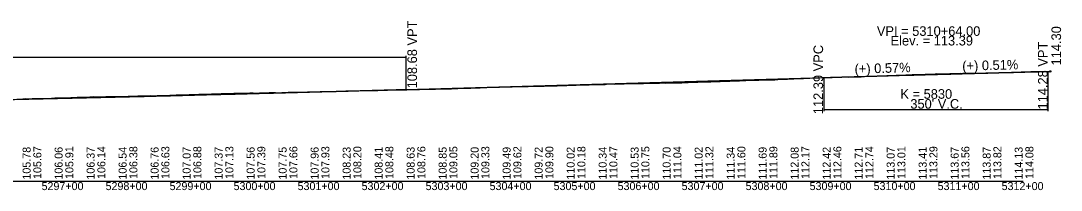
# Model space of a CAD drawing. Extents: x 2121671 to 2169879, y 557274 to 599957.
# Drawn here: x 2159202 to 2160827, y 598693 to 598958 of the extents above; entities that cross this region are included whole.
import ezdxf

# ---------------------------------------------------------------- set-up
doc = ezdxf.new("R2010")
doc.units = 0
for name, color, linetype in [('RD_DDB_GradeTX', 7, 'Continuous'), ('RD_DDB_Profile_EX', 7, 'Continuous'), ('RD_DDB_Profile_Lbl', 7, 'Continuous'), ('RD_DDB_Profile_PR', 7, 'Continuous'), ('RD_DDB_StaTX', 7, 'Continuous'), ('RD_DDB_StripGrade', 7, 'Continuous'), ('RD_DDB_VCLbl', 7, 'Continuous'), ('RD_GPK_Profile_Cell', 7, 'Continuous')]:
    doc.layers.add(name, color=color, linetype=linetype)

msp = doc.modelspace()

# ---------------------------------------------------------------- linework, layer by layer
at = {"layer": 'RD_DDB_GradeTX'}
for p, q in [((2160570.3, 598872.7), (2160631.2, 598874.4)), ((2160694.2, 598876), (2160633.2, 598874.4))]:
    msp.add_line(p, q, dxfattribs=at)
for centre in [(2160632.2, 598874.4), (2160810.4, 598878.9)]:
    msp.add_circle(centre, 1, dxfattribs=at)
at = {"layer": 'RD_DDB_Profile_EX'}
for points in [[(2160504.8, 598870.7), (2160509.8, 598870.7), (2160514.8, 598870.7), (2160519.8, 598871.2), (2160524.8, 598871.4), (2160529.8, 598871.6), (2160534.8, 598871.7), (2160539.8, 598871.9), (2160544.8, 598872), (2160549.8, 598872.2), (2160554.8, 598872.4), (2160559.8, 598872.6), (2160564.8, 598872.7), (2160569.8, 598872.8), (2160574.8, 598873.1), (2160579.8, 598873.3), (2160584.8, 598873.5), (2160589.8, 598873.8), (2160594.8, 598874), (2160599.8, 598874.2), (2160604.8, 598874.3), (2160609.8, 598874.3), (2160614.8, 598874.5), (2160619.8, 598874.5), (2160624.8, 598874.7), (2160629.8, 598874.8), (2160634.8, 598874.9), (2160639.8, 598874.9), (2160644.8, 598875.1), (2160649.8, 598875.3), (2160654.8, 598875.3), (2160659.8, 598875.3), (2160664.8, 598875.5), (2160669.8, 598876), (2160674.8, 598875.8), (2160679.8, 598875.7), (2160684.8, 598876), (2160689.8, 598876.1), (2160694.8, 598876.2), (2160699.8, 598876.3), (2160704.8, 598876.4), (2160709.8, 598876.5), (2160714.8, 598876.7), (2160719.8, 598876.9), (2160724.8, 598876.9), (2160729.8, 598877.1), (2160734.8, 598877.2), (2160739.8, 598877.2), (2160744.8, 598877.3), (2160749.8, 598877.5), (2160754.8, 598877.6), (2160759.8, 598877.9), (2160764.8, 598878), (2160769.8, 598878.1), (2160774.8, 598878.4), (2160779.8, 598878.6), (2160784.8, 598878.8), (2160789.8, 598878.9), (2160794.8, 598879), (2160799.8, 598879), (2160804.8, 598878.9), (2160809.8, 598878.9), (2160810.4, 598878.9)], [(2160004.8, 598855.9), (2160009.8, 598856), (2160014.8, 598856), (2160019.8, 598856.1), (2160024.8, 598856.3), (2160029.8, 598856.4), (2160034.8, 598856.5), (2160039.8, 598856.6), (2160044.8, 598856.8), (2160049.8, 598856.8), (2160054.8, 598857.1), (2160059.8, 598857.3), (2160064.8, 598857.4), (2160069.8, 598857.6), (2160074.8, 598857.7), (2160079.8, 598858), (2160084.8, 598858.1), (2160089.8, 598858.2), (2160094.8, 598858.3), (2160099.8, 598858.4), (2160104.8, 598858.5), (2160109.8, 598858.6), (2160114.8, 598858.7), (2160119.8, 598859.4), (2160124.8, 598859.3), (2160129.8, 598859.2), (2160134.8, 598859.4), (2160139.8, 598859.6), (2160144.8, 598859.7), (2160149.8, 598859.8), (2160154.8, 598859.9), (2160159.8, 598859.9), (2160164.8, 598860.1), (2160169.8, 598860.2), (2160174.8, 598860.2), (2160179.8, 598860.5), (2160184.8, 598860.4), (2160189.8, 598860.4), (2160194.8, 598860.6), (2160199.8, 598860.8), (2160204.8, 598860.9), (2160209.8, 598860.8), (2160214.8, 598860.9), (2160219.8, 598861), (2160224.8, 598861.1), (2160229.8, 598861.2), (2160234.8, 598861.3), (2160239.8, 598861.7), (2160244.8, 598861.7), (2160249.8, 598861.9), (2160254.8, 598862.2), (2160259.8, 598862.3), (2160264.8, 598862.5), (2160269.8, 598862.6), (2160274.8, 598862.8), (2160279.8, 598862.8), (2160284.8, 598863), (2160289.8, 598863.2), (2160294.8, 598863.4), (2160299.8, 598863.8), (2160304.8, 598863.9), (2160309.8, 598863.9), (2160314.8, 598864), (2160319.8, 598864.2), (2160324.8, 598864.4), (2160329.8, 598864.5), (2160334.8, 598864.8), (2160339.8, 598865), (2160344.8, 598865.1), (2160349.8, 598865.3), (2160354.8, 598865.4), (2160359.8, 598865.7), (2160364.8, 598865.9), (2160369.8, 598866), (2160374.8, 598865.6), (2160379.8, 598866), (2160384.8, 598866.4), (2160389.8, 598866.6), (2160394.8, 598866.8), (2160399.8, 598867), (2160404.8, 598867.2), (2160409.8, 598867.5), (2160414.8, 598867.7), (2160419.8, 598867.9), (2160424.8, 598868.1), (2160429.8, 598868.3), (2160434.8, 598868.5), (2160439.8, 598868.7), (2160444.8, 598868.8), (2160449.8, 598868.9), (2160454.8, 598869.2), (2160459.8, 598869.6), (2160464.8, 598869.6), (2160469.8, 598869.6), (2160474.8, 598869.8), (2160479.8, 598869.9), (2160484.8, 598870), (2160489.8, 598870.2), (2160494.8, 598870.1), (2160499.8, 598870.5), (2160504.8, 598870.7)], [(2159199.8, 598835.7), (2159204.8, 598836), (2159209.8, 598836.4), (2159214.8, 598836.3), (2159219.8, 598836.4), (2159224.8, 598836.5), (2159229.8, 598836.7), (2159234.8, 598836.8), (2159239.8, 598836.8), (2159244.8, 598836.4), (2159249.8, 598837.2), (2159254.8, 598837.4), (2159259.8, 598837.5), (2159264.8, 598837.7), (2159269.8, 598837.8), (2159274.8, 598837.9), (2159279.8, 598838.1), (2159284.8, 598838.3), (2159289.8, 598838.5), (2159294.8, 598838.7), (2159299.8, 598838.8), (2159304.8, 598838.9), (2159309.8, 598839.1), (2159314.8, 598839.6), (2159319.8, 598839.2), (2159324.8, 598839.3), (2159329.8, 598839.3), (2159334.8, 598839.5), (2159339.8, 598839.7), (2159344.8, 598839.8), (2159349.8, 598839.9), (2159354.8, 598840), (2159359.8, 598840), (2159364.8, 598840), (2159369.8, 598840.2), (2159374.8, 598840.4), (2159379.8, 598840.5), (2159384.8, 598840.6), (2159389.8, 598840.7), (2159394.8, 598840.8), (2159399.8, 598840.9), (2159404.8, 598841.1), (2159409.8, 598841), (2159414.8, 598841.2), (2159419.8, 598841.3), (2159424.8, 598841.4), (2159429.8, 598841.5), (2159434.8, 598841.8), (2159439.8, 598841.9), (2159444.8, 598842.1), (2159449.8, 598842.2), (2159454.8, 598842.4), (2159459.8, 598842.5), (2159464.8, 598842.7), (2159469.8, 598842.8), (2159474.8, 598843), (2159479.8, 598843.2), (2159484.8, 598843.4), (2159489.8, 598843.5), (2159494.8, 598843.6), (2159499.8, 598843.8), (2159504.8, 598843.9)], [(2159504.8, 598843.9), (2159509.8, 598844.1), (2159514.8, 598844.2), (2159519.8, 598844.4), (2159524.8, 598844.5), (2159529.8, 598844.6), (2159534.8, 598844.7), (2159539.8, 598844.8), (2159544.8, 598844.9), (2159549.8, 598845), (2159554.8, 598845.1), (2159559.8, 598845.3), (2159564.8, 598845.4), (2159569.8, 598845.2), (2159574.8, 598845.5), (2159579.8, 598845.6), (2159584.8, 598845.7), (2159589.8, 598845.8), (2159594.8, 598845.9), (2159599.8, 598845.9), (2159604.8, 598845.4), (2159609.8, 598846.1), (2159614.8, 598846.2), (2159619.8, 598846.3), (2159624.8, 598846.3), (2159629.8, 598846.4), (2159634.8, 598846.4), (2159639.8, 598846.4), (2159644.8, 598846.5), (2159649.8, 598846.8), (2159654.8, 598846.9), (2159659.8, 598847), (2159664.8, 598847.2), (2159669.8, 598847.3), (2159674.8, 598847.4), (2159679.8, 598847.6), (2159684.8, 598847.7), (2159689.8, 598847.8), (2159694.8, 598848), (2159699.8, 598848.1), (2159704.8, 598848.3), (2159709.8, 598848.4), (2159714.8, 598848.6), (2159719.8, 598848.7), (2159724.8, 598848.7), (2159729.8, 598848.8), (2159734.8, 598848.9), (2159739.8, 598849), (2159744.8, 598849), (2159749.8, 598849.1), (2159754.8, 598849.2), (2159759.8, 598849.3), (2159764.8, 598849.5), (2159769.8, 598849.6), (2159774.8, 598849.7), (2159779.8, 598849.9), (2159784.8, 598850), (2159789.8, 598850.1), (2159794.8, 598850.2), (2159799.8, 598850.3), (2159804.8, 598850.4), (2159809.8, 598850.5), (2159814.8, 598850.6), (2159819.8, 598850.7), (2159824.8, 598850.8), (2159829.8, 598851), (2159834.8, 598851.1), (2159839.8, 598851.2), (2159844.8, 598851.3), (2159849.8, 598851.3), (2159854.8, 598851.5), (2159859.8, 598851.6), (2159864.8, 598851.7), (2159869.8, 598851.8), (2159874.8, 598851.9), (2159879.8, 598852.1), (2159884.8, 598852.3), (2159889.8, 598852.5), (2159894.8, 598852.7), (2159899.8, 598852.8), (2159904.8, 598853), (2159909.8, 598853.2), (2159914.8, 598853.4), (2159919.8, 598853.5), (2159924.8, 598853.7), (2159929.8, 598853.9), (2159934.8, 598854.1), (2159939.8, 598854.2), (2159944.8, 598854.4), (2159949.8, 598854.5), (2159954.8, 598854.7), (2159959.8, 598854.9), (2159964.8, 598854.9), (2159969.8, 598855), (2159974.8, 598855.1), (2159979.8, 598855.2), (2159984.8, 598855.3), (2159989.8, 598855.4), (2159994.8, 598855.6), (2159999.8, 598855.7), (2160004.8, 598855.9)]]:
    msp.add_lwpolyline(points, dxfattribs=at)
at = {"layer": 'RD_DDB_Profile_PR'}
for p, q in [((2160807.2, 598878.9), (2160810.4, 598878.9)), ((2159803.2, 598850.9), (2160457.2, 598869.4))]:
    msp.add_line(p, q, dxfattribs=at)
for points in [[(2160457.2, 598869.4), (2160464.2, 598869.6), (2160471.2, 598869.8), (2160478.2, 598870), (2160485.2, 598870.2), (2160492.2, 598870.4), (2160499.2, 598870.6), (2160506.2, 598870.8), (2160513.2, 598871), (2160520.2, 598871.2), (2160527.2, 598871.4), (2160534.2, 598871.6), (2160541.2, 598871.8), (2160548.2, 598872), (2160555.2, 598872.2), (2160562.2, 598872.4), (2160569.2, 598872.6), (2160576.2, 598872.8), (2160583.2, 598873), (2160590.2, 598873.1), (2160597.2, 598873.3), (2160604.2, 598873.5), (2160611.2, 598873.7), (2160618.2, 598873.9), (2160625.2, 598874.1), (2160632.2, 598874.3), (2160639.2, 598874.5), (2160646.2, 598874.7), (2160653.2, 598874.8), (2160660.2, 598875), (2160667.2, 598875.2), (2160674.2, 598875.4), (2160681.2, 598875.6), (2160688.2, 598875.8), (2160695.2, 598876), (2160702.2, 598876.1), (2160709.2, 598876.3), (2160716.2, 598876.5), (2160723.2, 598876.7), (2160730.2, 598876.9), (2160737.2, 598877.1), (2160744.2, 598877.2), (2160751.2, 598877.4), (2160758.2, 598877.6), (2160765.2, 598877.8), (2160772.2, 598878), (2160779.2, 598878.1), (2160786.2, 598878.3), (2160793.2, 598878.5), (2160800.2, 598878.7), (2160807.2, 598878.9)], [(2158303.2, 598818.8), (2158333.2, 598819.2), (2158363.2, 598819.7), (2158393.2, 598820.1), (2158423.2, 598820.6), (2158453.2, 598821.1), (2158483.2, 598821.5), (2158513.2, 598822), (2158543.2, 598822.5), (2158573.2, 598823), (2158603.2, 598823.5), (2158633.2, 598824), (2158663.2, 598824.6), (2158693.2, 598825.1), (2158723.2, 598825.6), (2158753.2, 598826.2), (2158783.2, 598826.8), (2158813.2, 598827.3), (2158843.2, 598827.9), (2158873.2, 598828.5), (2158903.2, 598829.1), (2158933.2, 598829.7), (2158963.2, 598830.3), (2158993.2, 598830.9), (2159023.2, 598831.5), (2159053.2, 598832.2), (2159083.2, 598832.8), (2159113.2, 598833.5), (2159143.2, 598834.1), (2159173.2, 598834.8), (2159203.2, 598835.5), (2159233.2, 598836.2), (2159263.2, 598836.9), (2159293.2, 598837.6), (2159323.2, 598838.3), (2159353.2, 598839), (2159383.2, 598839.7), (2159413.2, 598840.5), (2159443.2, 598841.2), (2159473.2, 598842), (2159503.2, 598842.8), (2159533.2, 598843.5), (2159563.2, 598844.3), (2159593.2, 598845.1), (2159623.2, 598845.9), (2159653.2, 598846.7), (2159683.2, 598847.5), (2159713.2, 598848.3), (2159743.2, 598849.2), (2159773.2, 598850), (2159803.2, 598850.9)]]:
    msp.add_spline(points, degree=3, dxfattribs=at)
at = {"layer": 'RD_DDB_VCLbl'}
for p, q in [((2158303.2, 598900.9), (2159803.2, 598900.9)), ((2159803.2, 598903.4), (2159803.2, 598850.9)), ((2160807.2, 598816.9), (2160807.2, 598878.9)), ((2160457.2, 598816.9), (2160457.2, 598869.4)), ((2160457.2, 598819.4), (2160807.2, 598819.4))]:
    msp.add_line(p, q, dxfattribs=at)
at = {"layer": 'RD_GPK_Profile_Cell'}
msp.add_line((2157368.2, 598707.5), (2160768.2, 598707.5), dxfattribs=at)

# ---------------------------------------------------------------- texts
at = {"layer": 'RD_DDB_GradeTX'}
for s, rotation, p in [('(+) 0.57%', 1.6278, (2160504.8, 598875.3)), ('(+) 0.51%', 1.456, (2160673, 598880))]:
    msp.add_text(s, height=15, rotation=rotation, dxfattribs=at).set_placement(p)
at = {"layer": 'RD_DDB_Profile_Lbl'}
for s, p in [('VPI = 5310+64.00', (2160539.4, 598934.4)), ('Elev. = 113.39', (2160560.8, 598919.4))]:
    msp.add_text(s, height=15, dxfattribs=at).set_placement(p)
msp.add_text('114.30', height=15, rotation=90, dxfattribs=at).set_placement((2160827.2, 598888.2))
at = {"layer": 'RD_DDB_StaTX'}
for s, p in [('5297+00', (2159234.3, 598693.6)), ('5298+00', (2159334.3, 598693.6)), ('5299+00', (2159434.3, 598693.6)), ('5300+00', (2159534.3, 598693.6)), ('5301+00', (2159634.3, 598693.6)), ('5302+00', (2159734.3, 598693.6)), ('5303+00', (2159834.3, 598693.6)), ('5304+00', (2159934.3, 598693.6)), ('5305+00', (2160034.3, 598693.6)), ('5306+00', (2160134.3, 598693.6)), ('5307+00', (2160234.3, 598693.6)), ('5308+00', (2160334.3, 598693.6)), ('5309+00', (2160434.3, 598693.6)), ('5310+00', (2160534.3, 598693.6)), ('5311+00', (2160634.3, 598693.6)), ('5312+00', (2160734.3, 598693.6))]:
    msp.add_text(s, height=12.5, dxfattribs=at).set_placement(p)
at = {"layer": 'RD_DDB_StripGrade'}
for s, height, p in [('108.68 VPT', 15, (2159820.9, 598852.4)), ('114.28 VPT', 15, (2160806.2, 598819.4)), ('112.39 VPC', 15, (2160455.4, 598812.1)), ('105.78', 12.5, (2159217.2, 598710)), ('105.67', 12.5, (2159234, 598711)), ('106.06', 12.5, (2159267.2, 598710)), ('105.91', 12.5, (2159284, 598711)), ('106.14', 12.5, (2159334, 598711)), ('106.54', 12.5, (2159367.2, 598710)), ('106.38', 12.5, (2159384, 598711)), ('106.76', 12.5, (2159417.2, 598710)), ('106.63', 12.5, (2159434, 598711)), ('106.88', 12.5, (2159484, 598711)), ('107.13', 12.5, (2159534, 598711)), ('107.56', 12.5, (2159567.2, 598710)), ('107.39', 12.5, (2159584, 598711)), ('107.75', 12.5, (2159617.2, 598710)), ('107.66', 12.5, (2159634, 598711)), ('107.96', 12.5, (2159667.2, 598710)), ('107.93', 12.5, (2159684, 598711)), ('108.23', 12.5, (2159717.2, 598710)), ('108.20', 12.5, (2159734, 598711)), ('108.48', 12.5, (2159784, 598711)), ('108.63', 12.5, (2159817.2, 598710)), ('108.76', 12.5, (2159834, 598711)), ('108.85', 12.5, (2159867.2, 598710)), ('109.05', 12.5, (2159884, 598711)), ('109.20', 12.5, (2159917.2, 598710)), ('109.33', 12.5, (2159934, 598711)), ('109.62', 12.5, (2159984, 598711)), ('109.90', 12.5, (2160034, 598711)), ('110.18', 12.5, (2160084, 598711)), ('110.34', 12.5, (2160117.2, 598710)), ('110.47', 12.5, (2160134, 598711)), ('110.53', 12.5, (2160167.2, 598710)), ('110.75', 12.5, (2160184, 598711)), ('110.70', 12.5, (2160217.2, 598710)), ('111.04', 12.5, (2160234, 598711)), ('111.32', 12.5, (2160284, 598711)), ('111.34', 12.5, (2160317.2, 598710)), ('111.60', 12.5, (2160334, 598711)), ('111.89', 12.5, (2160384, 598711)), ('112.08', 12.5, (2160417.2, 598710)), ('112.17', 12.5, (2160434, 598711)), ('112.46', 12.5, (2160484, 598711)), ('112.74', 12.5, (2160534, 598711)), ('113.01', 12.5, (2160584, 598711)), ('113.29', 12.5, (2160634, 598711)), ('113.56', 12.5, (2160684, 598711)), ('113.82', 12.5, (2160734, 598711)), ('114.13', 12.5, (2160767.2, 598710)), ('114.08', 12.5, (2160784, 598711)), ('106.37', 12.5, (2159317.2, 598710)), ('107.07', 12.5, (2159467.2, 598710)), ('107.37', 12.5, (2159517.2, 598710)), ('108.41', 12.5, (2159767.2, 598710)), ('109.49', 12.5, (2159967.2, 598710)), ('109.72', 12.5, (2160017.2, 598710)), ('110.02', 12.5, (2160067.2, 598710)), ('111.02', 12.5, (2160267.2, 598710)), ('111.69', 12.5, (2160367.2, 598710)), ('112.42', 12.5, (2160467.2, 598710)), ('112.71', 12.5, (2160517.2, 598710)), ('113.07', 12.5, (2160567.2, 598710)), ('113.41', 12.5, (2160617.2, 598710)), ('113.67', 12.5, (2160667.2, 598710)), ('113.87', 12.5, (2160717.2, 598710))]:
    msp.add_text(s, height=height, rotation=90, dxfattribs=at).set_placement(p)
at = {"layer": 'RD_DDB_VCLbl'}
for s, p in [('K = 5830', (2160576.2, 598836.2)), ("350' V.C.", (2160591.7, 598820.7))]:
    msp.add_text(s, height=15, dxfattribs=at).set_placement(p)

doc.saveas('drawing.dxf')
